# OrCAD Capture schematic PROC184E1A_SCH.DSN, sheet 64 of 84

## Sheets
64 71. OVER VOLTAGE PROTECTION CKT: size C; title: OVER VOLTAGE PROTECTION CKT; note: PROC184_SCH
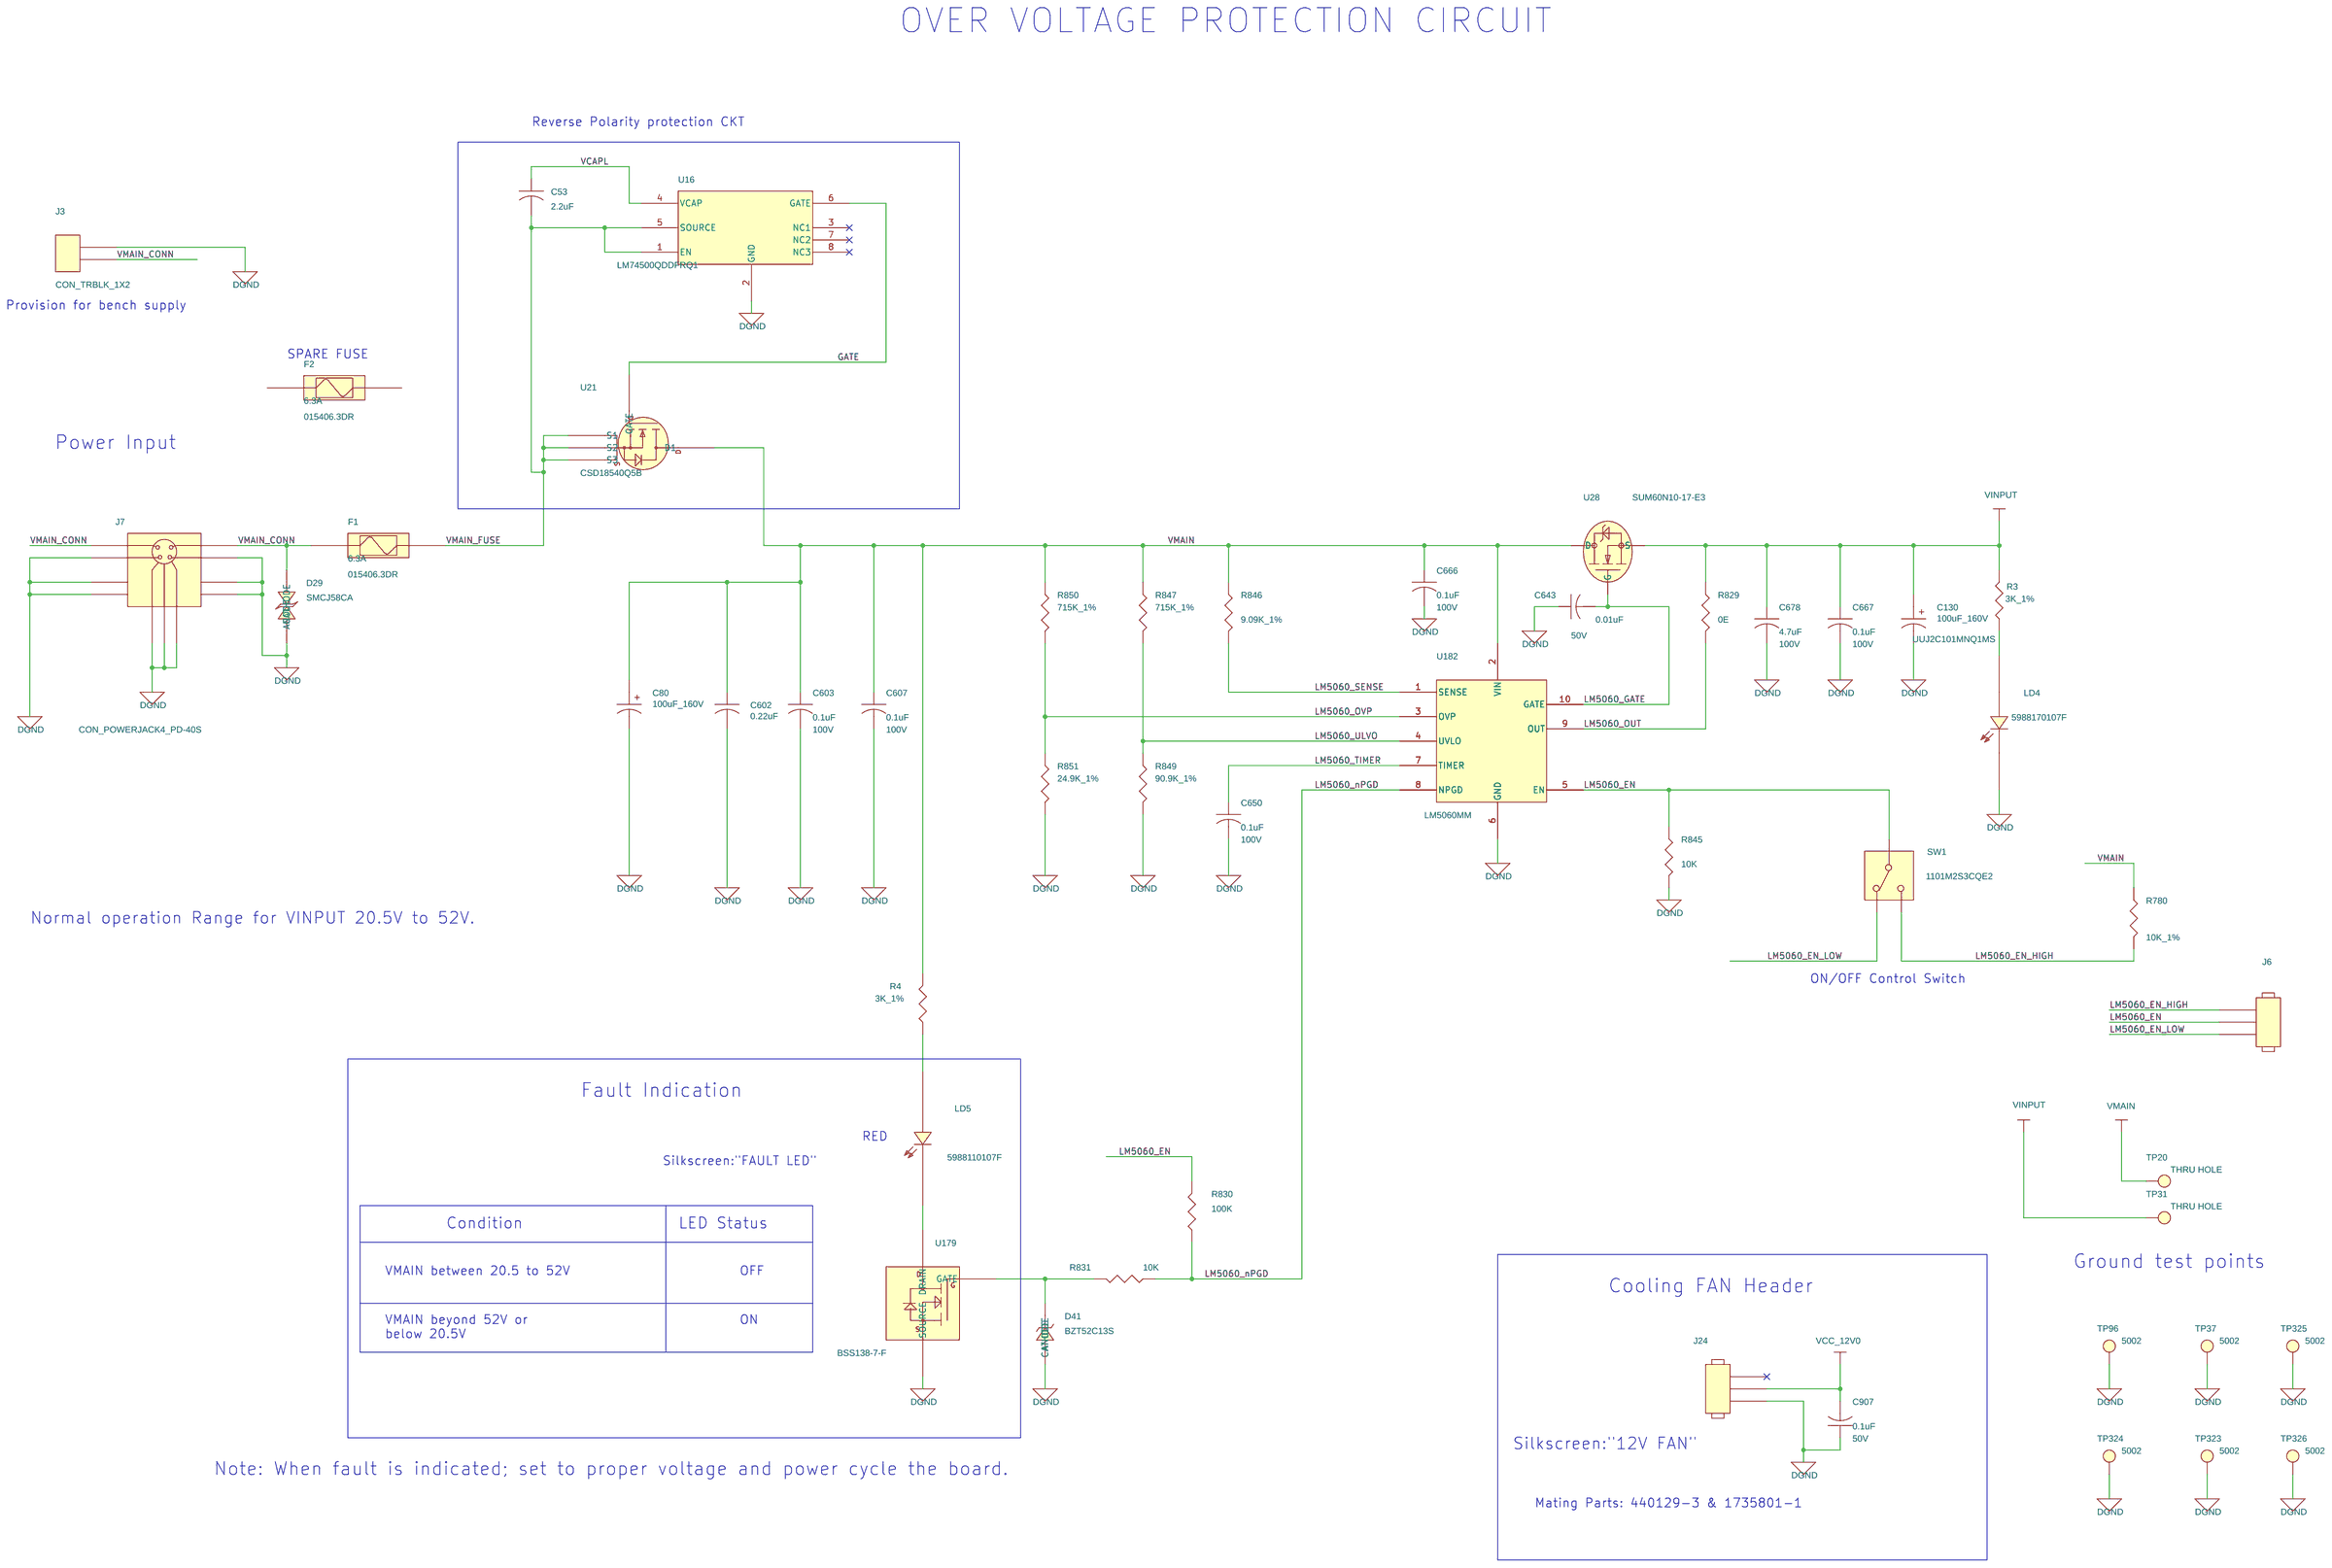
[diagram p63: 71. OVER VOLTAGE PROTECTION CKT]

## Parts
C53  2.2uF  [CAP1210_2-75]
C80  100uF_160V  [CAPAE_CASE173173_22-5]
C130  100uF_160V  [CAPAE_CASE173173_22-5]
C602  0.22uF  [CAP1206_1-25]
C603  0.1uF  [CAP0603_1]
C607  0.1uF  [CAP0603_1]
C643  0.01uF  [CAP0402_0-75]
C650  0.1uF  [CAP0603_1]
C666  0.1uF  [CAP0603_1]
C667  0.1uF  [CAP0603_1]
C678  4.7uF  [CAP1206_2]
C907  0.1uF  [CAP0402_0-75]
D29  SMCJ58CA  [DIO_SMC_2-7]
D41  BZT52C13S  [DIO_SOD323]
F1  6.3A  [FUSEH_154004_380X200_SMD_3-9]
F2  6.3A  [FUSEH_154004_380X200_SMD_3-9]
J3  CON_TRBLK_1X2  [CON_TB1X2_1803277_P_R_T_7-3]
J6  HDR_1X3  [HDR_3X1_100_S_T]
J7  CON_POWERJACK4_PD-40S  [CON_POWERJACK4_PD-40S_S_R_T_15]
J24  HDR_1X3  [HDR_1X3_440054-3_S_T_6-4]
LD4  5988170107F  [LED_0805_0-7]
LD5  5988110107F  [LED_0805]
R3  3K_1%  [RES0402_0-5]
R4  3K_1%  [RES0402_0-5]
R780  10K_1%  [RES0402_0-5]
R829  0E  [RES0402_0-5]
R830  100K  [RES0402_0-5]
R831  10K  [RES0402_0-5]
R845  10K  [RES0402_0-5]
R846  9.09K_1%  [RES0402_0-5]
R847  715K_1%  [RES0402_0-5]
R849  90.9K_1%  [RES0402_0-5]
R850  715K_1%  [RES0402_0-5]
R851  24.9K_1%  [RES0402_0-5]
SW1  1101M2S3CQE2  [SW3_185_500X260_TH_13]
TP20  THRU HOLE  [TP_40X65]
TP31  THRU HOLE  [TP_40X65]
TP37  5002  [TP_CIR67D40_TH_4-6]
TP96  5002  [TP_CIR67D40_TH_4-6]
TP323  5002  [TP_CIR67D40_TH_4-6]
TP324  5002  [TP_CIR67D40_TH_4-6]
TP325  5002  [TP_CIR67D40_TH_4-6]
TP326  5002  [TP_CIR67D40_TH_4-6]
U16  LM74500QDDFRQ1  [SOT23-8_1-1]
U21  CSD18540Q5B  [VSON8_CSD1850_240X200_1-1]
U28  SUM60N10-17-E3  [D2PAK-3]
U179  BSS138-7-F  [SOT23-123_1-1]
U182  LM5060MM  [MSOP10_19-68_120X120_1-1]

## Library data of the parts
C53 = CAP: CAP CERAMIC 2.2uF 100V 10% X7R 1210; Chkd/date: BAVISH/020811; Crtd /date: CHAITHANYA/290711; Custom_Duty: 15%; Customs_HS_Code: 85322990; Distributor_name: DIGIKEY; Distributor_part_number: 490-3385-1-ND; Footprint Path: Y:\MIS_DATABASE\Library\ALTIUM_TOOL\PCB_FOOTPRINTS\Altium_Footprint_Lib.PcbLib; Height: 2.70MM; Library Path: Y:\MIS_DATABASE\Library\ALTIUM_TOOL\SCHEMATICS_PARTS\MS_DISCRETE_Library.schlib; Manufacturer: MURATA; Mfr_name: MURATA; Mfr_part_number: GRM32ER72A225KA35L; Mistral Part No: 120011080001-R; Package: 1210; Part_type: CAPACITORS\CERAMIC; Project: ACRO_DM3730; RoHS: RoHS; Temperature: -55°C+125°C; Tolerance: 10%; Voltage: 100V; Wattage: NA; Weight: 110mg; Datasheet: Y:\MIS_DATABASE\DATASHEETS\CAPACITORS\MURATA-GXX-SER_NOV17.PDF
C80 C130 = CAP_POL: CAP ELECTROLYTIC 100uF 160V 20% CASE_173173; Chkd/date: MANIRAJA/110222; Crtd /date: ALVY/100222; Custom_Duty: 15%; Customs_HS_Code: 85322990; Distributor_name: MOUSER; Distributor_part_number: 647-UUJ2C101MNQ1MS; Footprint Path: Y:\MIS_DATABASE\Library\ALTIUM_TOOL\PCB_FOOTPRINTS\Altium_Footprint_Lib.PcbLib; Height: 22.50MM; Library Path: Y:\MIS_DATABASE\Library\ALTIUM_TOOL\SCHEMATICS_PARTS\MS_DISCRETE_Library.schlib; Manufacturer: NICHICON; Mfr_name: NICHICON; Mfr_part_number: UUJ2C101MNQ1MS; Mistral Part No: 120022020007-R; Package: CASE_173173; Part_type: CAPACITORS\ELECTROLYTIC; Project: TI_J7AHP_EVM_BRD; RoHS: RoHS; Temperature: -40°C+105°C; Tolerance: 20%; Voltage: 160V; Wattage: NA; Weight: 6170mg; Datasheet: Y:\MIS_DATABASE\DATASHEETS\CAPACITORS\UUJ-SER.PDF
C602 = CAP: CAP CERAMIC 0.22uF 100V 10% X7R 1206; Chkd/date: MAZHAR/151208; Crtd /date: USMAN/311008; Custom_Duty: 15%; Customs_HS_Code: 85322990; Distributor_name: DIGIKEY; Distributor_part_number: 490-3366-1-ND; Footprint Path: Y:\MIS_DATABASE\Library\ALTIUM_TOOL\PCB_FOOTPRINTS\Altium_Footprint_Lib.PcbLib; Height: 1.25MM; Library Path: Y:\MIS_DATABASE\Library\ALTIUM_TOOL\SCHEMATICS_PARTS\MS_DISCRETE_Library.schlib; Manufacturer: MURATA; Mfr_name: MURATA; Mfr_part_number: GRM31MR72A224KA01L; Mistral Part No: 120009030093-R; Package: 1206; Part_type: CAPACITORS\CERAMIC; Project: LADC_PB; RoHS: RoHS; Temperature: -55°C+125°C; Tolerance: 10%; Voltage: 100V; Wattage: NA; Weight: 40mg; Datasheet: Y:\MIS_DATABASE\DATASHEETS\CAPACITORS\MURATA-GXX-SER_NOV17.PDF
C603 C607 = CAP: CAP CERAMIC 0.1uF 100V 10% X7R 0603; Automotive Alternate_mfr_name: TDK; Automotive Alternate_mfr_part_number: CGA3E2X7R1H104K080AA; Chkd/date: MANIRAJA/170420; Crtd /date: ALVY/170420; Custom_Duty: 15%; Customs_HS_Code: 85322990; Direct Alternate_mfr_name: SAMSUNG; Direct Alternate_mfr_part_number: CL10B104JB8NNNC; Distributor_name: DIGIKEY; Distributor_part_number: 490-3285-1-ND; Footprint Path: Y:\MIS_DATABASE\Library\ALTIUM_TOOL\PCB_FOOTPRINTS\Altium_Footprint_Lib.PcbLib; Height: 0.90MM; Library Path: Y:\MIS_DATABASE\Library\ALTIUM_TOOL\SCHEMATICS_PARTS\MS_DISCRETE_Library.schlib; Manufacturer: MURATA; Mfr_name: MURATA; Mfr_part_number: GRM188R72A104KA35D; Mistral Part No: 120017010012-R; Package: 0603; Part_type: CAPACITORS\CERAMIC; Project: CUSTOM DCA1000; RoHS: RoHS; Temperature: -55°C+125°C; Tolerance: 10%; Voltage: 100V; Wattage: NA; Weight: 6.3mg; Datasheet: Y:\MIS_DATABASE\DATASHEETS\CAPACITORS\GRM188R72A104KA35.PDF
C643 = CAP: CAP CERAMIC 0.01uF 50V 10% X7R 0402; Assembly_Instruction: DNI; Automotive Alternate_mfr_name: TDK; Automotive Alternate_mfr_part_number: CGA2B3X7R1H103K050BB; Chkd/date: MANIRAJA/280319; Crtd /date: MANIRAJA/280319; Custom_Duty: 15%; Customs_HS_Code: 85322990; Direct Alternate_mfr_name: TDK; Direct Alternate_mfr_part_number: C1005X7R1H103K050BE; Distributor_name: DIGIKEY; Distributor_part_number: 490-4516-1-ND; Footprint Path: Y:\MIS_DATABASE\Library\ALTIUM_TOOL\PCB_FOOTPRINTS\Altium_Footprint_Lib.PcbLib; Height: 0.55MM; Library Path: Y:\MIS_DATABASE\Library\ALTIUM_TOOL\SCHEMATICS_PARTS\MS_DISCRETE_Library.schlib; Manufacturer: MURATA; Mfr_name: MURATA; Mfr_part_number: GRM155R71H103KA88D; Mistral Part No: 120009030025-R; Package: 0402; Part_type: CAPACITORS\CERAMIC; Project: G4_SVGA; RoHS: RoHS; Temperature: -55°C+125°C; Tolerance: 10%; Voltage: 50V; Wattage: NA; Weight: 0.65mg; Datasheet: Y:\MIS_DATABASE\DATASHEETS\CAPACITORS\GRM155R71H103KA88D.PDF
C650 C666 C667 = CAP: CAP CERAMIC 0.1uF 100V 10% X7R 0603; Automotive Alternate_mfr_name: TDK; Automotive Alternate_mfr_part_number: CGA3E2X7R1H104K080AA; Chkd/date: MANIRAJA/170420; Crtd /date: ALVY/170420; Custom_Duty: 15%; Customs_HS_Code: 85322990; DescriptiveText: CAP CERAMIC 0.1uF 100V 10% X7R 0603; Direct Alternate_mfr_name: SAMSUNG; Direct Alternate_mfr_part_number: CL10B104JB8NNNC; Distributor_name: DIGIKEY; Distributor_part_number: 490-3285-1-ND; Footprint Path: Y:\MIS_DATABASE\Library\ALTIUM_TOOL\PCB_FOOTPRINTS\Altium_Footprint_Lib.PcbLib; Height: 0.90MM; Library Path: Y:\MIS_DATABASE\Library\ALTIUM_TOOL\SCHEMATICS_PARTS\MS_DISCRETE_Library.schlib; Manufacturer: MURATA; Mfr: YAGEO AMERICA; MfrNum: CC0603KRX7R0BB104; Mfr_name: MURATA; Mfr_part_number: GRM188R72A104KA35D; Mistral Part No: 120017010012-R; Mistral part number: NSPN00374; Package: 0603; Part_type: CAPACITORS\CERAMIC; Project: CUSTOM DCA1000; RoHS: RoHS; Temperature: -55°C+125°C; Tolerance: 10%; Voltage: 100V; Wattage: NA; Weight: 6.3mg; Datasheet: Y:\MIS_DATABASE\DATASHEETS\CAPACITORS\GRM188R72A104KA35.PDF
C678 = CAP: CAP CERAMIC 4.7uF 100V 10% X7S 1206; Automotive Alternate_mfr_name: TDK; Automotive Alternate_mfr_part_number: CGA4J1X7R1H475K125AC; Chkd/date: MANIRAJA/121020; Crtd /date: ALVY/091020; Custom_Duty: 15%; Customs_HS_Code: 85322990; Direct Alternate_mfr_name: MURATA; Direct Alternate_mfr_part_number: GRM21BR61H475KE51L; Distributor_name: DIGIKEY; Distributor_part_number: 490-18620-1-ND; Footprint Path: Y:\MIS_DATABASE\Library\ALTIUM_TOOL\PCB_FOOTPRINTS\Altium_Footprint_Lib.PcbLib; Height: 1.90MM; Library Path: Y:\MIS_DATABASE\Library\ALTIUM_TOOL\SCHEMATICS_PARTS\MS_DISCRETE_Library.schlib; Manufacturer: MURATA; Mfr_name: MURATA; Mfr_part_number: GRM31CC72A475KE11L; Mistral Part No: 120020100021-R; Package: 1206; Part_type: CAPACITORS\CERAMIC; Project: ECU_RO; RoHS: RoHS; Temperature: -55°C+125°C; Tolerance: 10%; Voltage: 100V; Wattage: NA; Weight: 64mg; Datasheet: Y:\MIS_DATABASE\DATASHEETS\CAPACITORS\GRM31CC72A475KE11.PDF
C907 = CAP: CAP CERAMIC 0.1uF 50V 10% X7R 0402; Automotive Alternate_mfr_name: TDK; Automotive Alternate_mfr_part_number: CGA2B3X7R1H104K050BB; Chkd/date: MANIRAJA/261020; Crtd /date: ALVY/211020; Custom_Duty: 15%; Customs_HS_Code: 85322990; Direct Alternate_mfr_name: TDK; Direct Alternate_mfr_part_number: C1005X7R1H104K050BE; Distributor_name: DIGIKEY; Distributor_part_number: 490-10700-1-ND; Footprint Path: Y:\MIS_DATABASE\Library\ALTIUM_TOOL\PCB_FOOTPRINTS\Altium_Footprint_Lib.PcbLib; Height: 0.55MM; Library Path: Y:\MIS_DATABASE\Library\ALTIUM_TOOL\SCHEMATICS_PARTS\MS_DISCRETE_Library.schlib; Manufacturer: MURATA; Mfr_name: MURATA; Mfr_part_number: GRM155R71H104KE14D; Mistral Part No: 120011100014-R; Package: 0402; Part_type: CAPACITORS\CERAMIC; Project: J7_CP; RoHS: RoHS; Temperature: -55°C+125°C; Tolerance: 10%; Voltage: 50V; Wattage: NA; Weight: 3.1mg; Datasheet: Y:\MIS_DATABASE\DATASHEETS\CAPACITORS\GRM155R71H104KE14.PDF
D29 = DIODE_TVS_DUAL: DIODE TVS BI-DIR 1500W 58V SMC; Chkd/date: ALVY/210222; Crtd /date: TAMILARASU/210222; Custom_Duty: 15%; Customs_HS_Code: 85412900; Distributor_name: DIGIKEY; Distributor_part_number: SMCJ58CALFCT-ND; Footprint Path: Y:\MIS_DATABASE\Library\ALTIUM_TOOL\PCB_FOOTPRINTS\Altium_Footprint_Lib.PcbLib; Height: 2.62MM; Library Path: Y:\MIS_DATABASE\Library\ALTIUM_TOOL\SCHEMATICS_PARTS\MS_DISCRETE_Library.schlib; Manufacturer: LITTELFUSE; Mfr_name: LITTELFUSE; Mistral Part No: 130022020036-R; Package: SMC; Part_type: DIODE\TVS; Project: TI_J7AHP_EVM_BRD; RoHS: RoHS; Temperature: -65°C+150°C; Tolerance: NA; Voltage: 58V; Wattage: NA; Weight: 210mg; Datasheet: Y:\MIS_DATABASE\DATASHEETS\DISCRETES\DIODES\LF-SMCJ-SER.PDF
D41 = DIODE_ZENER: DIODE ZENER 13V 200mW SOD323; Chkd/date: MAZHAR/101210; Crtd /date: BAVISH/101210; Custom_Duty: 15%; Customs_HS_Code: 85412900; Distributor_name: DIGIKEY; Distributor_part_number: BZT52C13S-FDICT-ND; Height: 1.05MM; Manufacturer: DIODES INC; Mfr_name: DIODES INC; Mfr_part_number: BZT52C13S-7-F; Mistral Part No: 130010120013-R; Package: SOD323; Part_type: DIODE\ZENER; Project: IEMS; RoHS: RoHS; Temperature: -65°C+150°C; Tolerance: NA; Voltage: NA; Wattage: 200mW; Weight: 0.004g; Datasheet: Y:\MIS_DATABASE\DATASHEETS\DISCRETES\DIODES\BZT52C.PDF
F1 F2 = FUSE_HOLDER_0154: FUSE AND HOLDER BLOK 6.3A SMD; Chkd/date: USMAN/280612; Crtd /date: BAVISH/040811; Custom_Duty: NA; Customs_HS_Code: NA; Distributor_name: DIGIKEY; Distributor_part_number: F3152CT-ND; Footprint Path: Y:\MIS_DATABASE\Library\ALTIUM_TOOL\PCB_FOOTPRINTS\Altium_Footprint_Lib.PcbLib; Height: 3.81MM; Library Path: Y:\MIS_DATABASE\Library\ALTIUM_TOOL\SCHEMATICS_PARTS\MS_DISCRETE_Library.schlib; Mfr_name: LITTLE FUSE; Mfr_part_number: 015406.3DR; Mistral Part No: 130011080014-R; Package: SMD; Part_type: FUSE; Project: GEMYC; RoHS: RoHS; Temperature: -55°C+125°C; Tolerance: NA; Voltage: NA; Wattage: NA; Weight: NA; Datasheet: Y:\MIS_DATABASE\DATASHEETS\MISC\FUSE\0154X-SER.PDF
J3 = CON_TRBLK_2X1: CON TERMINAL BLOCKS 1X2 3.81MM PITCH MALE RT TH; Chkd/date: ALVY/140322; Crtd /date: TAMILARASU/110322; Custom_Duty: 24%; Customs_HS_Code: 85369090; Distributor_name: DIGIKEY; Distributor_part_number: 277-1206-ND; Footprint Path: Y:\MIS_DATABASE\Library\ALTIUM_TOOL\PCB_FOOTPRINTS\Altium_Footprint_Lib.PcbLib; Height: 7.25MM; Library Path: Y:\MIS_DATABASE\Library\ALTIUM_TOOL\SCHEMATICS_PARTS\MS_CONNECTOR_Library.schlib; Mfr_name: PHOENIX; Mfr_part_number: 1803277; Mistral Part No: 150022030013-R; Package: THRU-HOLE; Part_type: CONNECTOR\TERMINAL BLOCK; Project: TI_J7AHP_EVM_BRD; RoHS: RoHS; Temperature: NA; Tolerance: NA; Voltage: NA; Wattage: NA; Weight: 784mg; Datasheet: Y:\MIS_DATABASE\DATASHEETS\CONNECTORS\1803277.PDF
J6 = HEADER_3X1: HDR 1X3 2.54MM PITCH ST TH; Assembly_Instruction: DNI; Chkd/date: VASANTHA/290616; Crtd /date: VASANTHA/290616; Custom_Duty: 15%; Customs_HS_Code: 85322990; Distributor_name: DIGIKEY; Distributor_part_number: 609-3471-ND; Height: 8.58MM; Manufacturer: FCI; Mfr_name: FCI; Mfr_part_number: 68001-403HLF; Mistral Part No: 150016060025-R; Package: THRU-HOLE; Part_type: CONNECTOR\HEADERS; Project: IKEYP; RoHS: RoHS; Temperature: -40°C+105°C; Tolerance: NA; Voltage: NA; Wattage: NA; Weight: NA; Datasheet: Y:\MIS_DATABASE\DATASHEETS\CONNECTORS\68000.PDF
J7 = CON_POWERJACK_PD-40S: CON POWER JACK 4POS FEMALE RT TH; Chkd/date: VASANTHA/140616; Crtd /date: VASANTHA/140616; Custom_Duty: 24%; Customs_HS_Code: 85369090; Distributor_name: DIGIKEY; Distributor_part_number: CP-7240-ND; Height: 15.00MM; Manufacturer: CUI INC; Mfr_name: CUI INC; Mfr_part_number: PD-40S; Mistral Part No: 150016060015-R; Package: THRU-HOLE; Part_type: CONNECTOR\JACK; Project: NTR_GPSDO BOX CARD; RoHS: RoHS; Temperature: NA; Tolerance: NA; Voltage: NA; Wattage: NA; Weight: NA; Datasheet: Y:\MIS_DATABASE\DATASHEETS\CONNECTORS\PD-40S.PDF
J24 = HEADER_3X1: CON HDR 1X3 2.00MM PITCH ST TH; Chkd/date: MANIRAJA/261017; Crtd /date: MANIRAJA/261017; Custom_Duty: 24%; Customs_HS_Code: 85369090; Distributor_name: DIGIKEY; Distributor_part_number: A100035-ND; Height: 6.35MM; Manufacturer: TE CONNECTIVITY; Mfr_name: TE CONNECTIVITY; Mfr_part_number: 440054-3; Mistral Part No: 150017100038-R; Package: THRU-HOLE; Part_type: CONNECTOR\HEADERS; Project: TI_MAXIE_CPB; RoHS: RoHS; Temperature: -25°C+85°C; Tolerance: NA; Voltage: NA; Wattage: NA; Weight: NA; Datasheet: Y:\MIS_DATABASE\DATASHEETS\CONNECTORS\440054XXX.PDF
LD4 = LED_598-8170-107F: LED ALINGAP GREEN CLEAR 0805; Chkd/date: MANIRAJA/230817; Crtd /date: SARANYA/070514; Custom_Duty: 24%; Customs_HS_Code: 85437099; Distributor_name: DIGIKEY; Distributor_part_number: 350-2044-1-ND; Footprint Path: Y:\MIS_DATABASE\Library\ALTIUM_TOOL\PCB_FOOTPRINTS\Altium_Footprint_Lib.PcbLib; Height: 0.70MM; Manufacturer: DIALIGHT; Mfr_name: DIALIGHT; Mistral Part No: 130014050065-R; Package: 0805; Part_type: OPTO\LED; Project: AEGIS GP BETA2; RoHS: RoHS; Temperature: -30°C+85°C; Tolerance: NA; Voltage: NA; Wattage: NA; Weight: NA; Datasheet: Y:\MIS_DATABASE\DATASHEETS\DISCRETES\LEDS\598-SER.PDF
LD5 = LED_598-8170-107F: LED ALINGAP RED CLEAR 0805 SMD; Chkd/date: BALACHANDAR/160514; Crtd /date: SARANYA/070514; Custom_Duty: 24%; Customs_HS_Code: 85437099; Distributor_name: DIGIKEY; Distributor_part_number: 350-2038-1-ND; Footprint Path: Y:\MIS_DATABASE\Library\ALTIUM_TOOL\PCB_FOOTPRINTS\Altium_Footprint_Lib.PcbLib; Height: 0.70MM; Manufacturer: DIALIGHT; Mfr_name: DIALIGHT; Mistral Part No: 130014050069-R; Package: 0805; Part_type: OPTO\LED; Project: AEGIS GP BETA2; RoHS: RoHS; Temperature: NA; Tolerance: NA; Voltage: NA; Wattage: NA; Weight: NA; Datasheet: Y:\MIS_DATABASE\DATASHEETS\DISCRETES\LEDS\598-SER.PDF
R3 R4 = RESISTOR: RES 3K 1/16W 1% 0402; Chkd/date: MANIRAJA/101117; Crtd /date: MANIRAJA/101117; Custom_Duty: 15%; Customs_HS_Code: 85332119; Distributor_name: DIGIKEY; Distributor_part_number: 311-3KLRCT-ND; Footprint Path: Y:\MIS_DATABASE\Library\ALTIUM_TOOL\PCB_FOOTPRINTS\Altium_Footprint_Lib.PcbLib; Height: 0.40MM; Library Path: Y:\MIS_DATABASE\Library\ALTIUM_TOOL\SCHEMATICS_PARTS\MS_DISCRETE_Library.schlib; Manufacturer: YAGEO AMERICA; Mfr_name: YAGEO AMERICA; Mfr_part_number: RC0402FR-073KL; Mistral Part No: 110017110004-R; Package: 0402; Part_type: RESISTORS\FIXED; Project: TI_SVB_MAXWELL_DUT; RoHS: RoHS; Temperature: -55°C+155°C; Tolerance: 1%; Voltage: NA; Wattage: 1/16W; Weight: 0.65mg; Datasheet: Y:\MIS_DATABASE\DATASHEETS\RESISTORS\RCXXXXL-SER_MAR18.PDF
R780 = RESISTOR: RES 10K 1/16W 1% 0402; Chkd/date: VASANTHA/201216; Crtd /date: GEETHA/290506; Custom_Duty: 15%; Customs_HS_Code: 85332119; Distributor_name: DIGIKEY; Distributor_part_number: 311-10.0KLRTR-ND; Footprint Path: Y:\MIS_DATABASE\Library\ALTIUM_TOOL\PCB_FOOTPRINTS\Altium_Footprint_Lib.PcbLib; Height: 0.40MM; Library Path: Y:\MIS_DATABASE\Library\ALTIUM_TOOL\SCHEMATICS_PARTS\MS_DISCRETE_Library.schlib; Manufacturer: YAGEO AMERICA; Mfr_name: YAGEO AMERICA; Mfr_part_number: RC0402FR-0710KL; Mistral Part No: 110015090015-R; Package: 0402; Part_type: RESISTORS\FIXED; Project: VOCERA; RoHS: RoHS; Temperature: -55°C+155°C; Tolerance: 1%; Voltage: NA; Wattage: 1/16W; Weight: 0.65mg; Datasheet: Y:\MIS_DATABASE\DATASHEETS\RESISTORS\RCXXXXL-SER_MAR18.PDF
R829 = RESISTOR: RES 0E 1/10W JUMPER 0402; Chkd/date: VASANTHA/061216; Crtd /date: NAVEED/201014; Custom_Duty: 15%; Customs_HS_Code: 85332119; Distributor_name: DIGIKEY; Distributor_part_number: P0.0JCT-ND; Footprint Path: Y:\MIS_DATABASE\Library\ALTIUM_TOOL\PCB_FOOTPRINTS\Altium_Footprint_Lib.PcbLib; Height: 0.40MM; IBISSP_MODLES: VALUE REPEATING 2 TIME; Library Path: Y:\MIS_DATABASE\Library\ALTIUM_TOOL\SCHEMATICS_PARTS\MS_DISCRETE_Library.schlib; Manufacturer: PANASONIC-ECG; Mfr_name: PANASONIC-ECG; Mfr_part_number: ERJ-2GE0R00X; Mistral Part No: 110018030052-R; Package: 0402; Part_type: RESISTORS\FIXED; Project: AEGIS POM; RoHS: RoHS; Temperature: -55°C+155°C; Tolerance: NA; Voltage: NA; Wattage: 1/10W; Weight: 0.8mg; Datasheet: Y:\MIS_DATABASE\DATASHEETS\RESISTORS\PAN-ERJSER_NOV17.PDF
R830 = RESISTOR: RES 100K 1/10W 5% 0402; Chkd/date: VASANTHA/291216; Crtd /date: GEETHA/190406; Custom_Duty: 15%; Customs_HS_Code: 85332119; Distributor_name: DIGIKEY; Distributor_part_number: P100KJCT-ND; Footprint Path: Y:\MIS_DATABASE\Library\ALTIUM_TOOL\PCB_FOOTPRINTS\Altium_Footprint_Lib.PcbLib; Height: 0.40MM; Library Path: Y:\MIS_DATABASE\Library\ALTIUM_TOOL\SCHEMATICS_PARTS\MS_DISCRETE_Library.schlib; Manufacturer: PANASONIC-ECG; Mfr_name: PANASONIC-ECG; Mfr_part_number: ERJ-2GEJ104X; Mistral Part No: 110009030177-R; Package: 0402; Part_type: RESISTORS\FIXED; Project: RED EYE; RoHS: RoHS; Temperature: -55°C+155°C; Tolerance: 5%; Voltage: NA; Wattage: 1/10W; Weight: 0.8mg; Datasheet: Y:\MIS_DATABASE\DATASHEETS\RESISTORS\PAN-ERJSER_NOV17.PDF
R831 R845 = RESISTOR: RES 10K 1/16W 5% 0402; Chkd/date: VASANTHA/061216; Crtd /date: MAZHAR/230805; Custom_Duty: 15%; Customs_HS_Code: 85332119; Distributor_name: DIGIKEY; Distributor_part_number: 311-10KJRCT-ND; Footprint Path: Y:\MIS_DATABASE\Library\ALTIUM_TOOL\PCB_FOOTPRINTS\Altium_Footprint_Lib.PcbLib; Height: 0.40MM; Library Path: Y:\MIS_DATABASE\Library\ALTIUM_TOOL\SCHEMATICS_PARTS\MS_DISCRETE_Library.schlib; Manufacturer: YAGEO AMERICA; Mfr_name: YAGEO AMERICA; Mfr_part_number: RC0402JR-0710KL; Mistral Part No: 110011060021-R; Package: 0402; Part_type: RESISTORS\FIXED; Project: HSE; RoHS: RoHS; Temperature: -55°C+155°C; Tolerance: 5%; Voltage: NA; Wattage: 1/16W; Weight: 0.65mg; Datasheet: Y:\MIS_DATABASE\DATASHEETS\RESISTORS\RCXXXXL-SER_MAR18.PDF
R846 = RESISTOR: RES 9.09K 1/16W 1% 0402; Chkd/date: VASANTHA/281216; Crtd /date: BAVISH/010611; Custom_Duty: 15%; Customs_HS_Code: 85332119; Distributor_name: DIGIKEY; Distributor_part_number: 541-9.09KLCT-ND; Footprint Path: Y:\MIS_DATABASE\Library\ALTIUM_TOOL\PCB_FOOTPRINTS\Altium_Footprint_Lib.PcbLib; Height: 0.40MM; Library Path: Y:\MIS_DATABASE\Library\ALTIUM_TOOL\SCHEMATICS_PARTS\MS_DISCRETE_Library.schlib; Manufacturer: VISHAY; Mfr_name: VISHAY; Mfr_part_number: CRCW04029K09FKED; Mistral Part No: 110011060006-R; Package: 0402; Part_type: RESISTORS\FIXED; Project: TE_MODULE; RoHS: RoHS; Temperature: -55°C+155°C; Tolerance: 1%; Voltage: NA; Wattage: 1/16W; Weight: 0.65mg; Datasheet: Y:\MIS_DATABASE\DATASHEETS\RESISTORS\CRCW0603.PDF
R847 R850 = RESISTOR: RES 715K 1/10W 1% 0402; Chkd/date: JEBRAN/040715; Crtd /date: JEBRAN/040715; Custom_Duty: 15%; Customs_HS_Code: 85332119; Distributor_name: DIGIKEY; Distributor_part_number: P715KLCT-ND; Footprint Path: Y:\MIS_DATABASE\Library\ALTIUM_TOOL\PCB_FOOTPRINTS\Altium_Footprint_Lib.PcbLib; Height: 0.40MM; Library Path: Y:\MIS_DATABASE\Library\ALTIUM_TOOL\SCHEMATICS_PARTS\MS_DISCRETE_Library.schlib; Mfr_name: PANASONIC-ECG; Mfr_part_number: ERJ-2RKF7153X; Mistral Part No: 110015070005-R; Package: 0402; Part_type: RESISTORS\FIXED; Project: CYPHY_FVB; RoHS: RoHS; Temperature: -55°C+155°C; Tolerance: 1%; Voltage: NA; Wattage: 1/10W; Weight: 0.8mg; Datasheet: Y:\MIS_DATABASE\DATASHEETS\RESISTORS\PAN-ERJSER_NOV17.PDF
R849 = RESISTOR: RES 90.9K 1/10W 1% 0402; Chkd/date: ALVY/210222; Crtd /date: TAMILARASU/210222; Custom_Duty: 15%; Customs_HS_Code: 85332119; Distributor_name: DIGIKEY; Distributor_part_number: 2019-RK73G1ETTP9092FCT-ND; Footprint Path: Y:\MIS_DATABASE\Library\ALTIUM_TOOL\PCB_FOOTPRINTS\Altium_Footprint_Lib.PcbLib; Height: 0.40MM; Library Path: Y:\MIS_DATABASE\Library\ALTIUM_TOOL\SCHEMATICS_PARTS\MS_DISCRETE_Library.schlib; Manufacturer: YAGEO AMERICA; Mfr_name: KOA SPEER; Mfr_part_number: RK73G1ETTP9092F; Mistral Part No: 110022020011-R; Package: 0402; Part_type: RESISTORS\FIXED; Project: TI_J7AHP_EVM_BRD; RoHS: RoHS; Temperature: -55°C+155°C; Tolerance: 1%; Voltage: NA; Wattage: 1/10W; Weight: 0.65mg; Datasheet: Y:\MIS_DATABASE\DATASHEETS\RESISTORS\RK73G-SER.PDF
R851 = RESISTOR: RES 24.9K 1/16W 1% 0402; Chkd/date: MANIRAJA/121017; Crtd /date: MANIRAJA/121017; Custom_Duty: 15%; Customs_HS_Code: 85332119; Distributor_name: DIGIKEY; Distributor_part_number: 311-24.9KLRCT-ND; Footprint Path: Y:\MIS_DATABASE\Library\ALTIUM_TOOL\PCB_FOOTPRINTS\Altium_Footprint_Lib.PcbLib; Height: 0.40MM; Library Path: Y:\MIS_DATABASE\Library\ALTIUM_TOOL\SCHEMATICS_PARTS\MS_DISCRETE_Library.schlib; Manufacturer: YAGEO AMERICA; Mfr_name: YAGEO AMERICA; Mfr_part_number: RC0402FR-0724K9L; Mistral Part No: 110009030538-R; Package: 0402; Part_type: RESISTORS\FIXED; Project: P4_RADAR_DI; RoHS: RoHS; Temperature: -55°C+155°C; Tolerance: 1%; Voltage: NA; Wattage: 1/16W; Weight: 0.65mg; Datasheet: Y:\MIS_DATABASE\DATASHEETS\RESISTORS\RCXXXXL-SER_MAR18.PDF
SW1 = SW3_SPDT_1101: SWITCH MINIATURE SLIDE SPDT VERTICAL TH; Chkd/date: VASANTHA/060117; Crtd /date: BAVISH/130711; Custom_Duty: 24%; Customs_HS_Code: 85369090; Distributor_name: DIGIKEY; Distributor_part_number: CKN5001-ND; Height: 12.98MM; Manufacturer: C&K COMPONENTS; Mfr_name: C&K COMPONENTS; Mistral Part No: 130011070018-R; Package: THRU-HOLE; Part_type: ELECTRO-MECHANICAL\SWITCH; Project: HMC_DEBUG; RoHS: RoHS; Temperature: -30°C+65°C; Tolerance: NA; Voltage: NA; Wattage: NA; Weight: NA; Datasheet: Y:\MIS_DATABASE\DATASHEETS\MISC\SWITCHES\1101-SERIES.PDF
TP20 TP31 = TESTPOINT: TESTPOINT 1.0MM DRILL PTH; Chkd/date: MAZHAR/271211; Crtd /date: SHREESHAIL/041005; Distributor_name: NA; Distributor_part_number: NA; Height: NA; Manufacturer: LOCAL; Mfr_name: LOCAL; Mistral Part No: 130009030938; Package: THRU-HOLE; Project: HSE; Datasheet: NA
TP37 TP96 TP323-TP326 = TESTPOINT: ACCESSORIE PC TEST POINT; Chkd/date: VASANTHA/121216; Crtd /date: MANIRAJA/121216; Custom_Duty: NA; Customs_HS_Code: NA; Distributor_name: DIGIKEY; Distributor_part_number: 36-5002-ND; Footprint Path: Y:\MIS_DATABASE\Library\ALTIUM_TOOL\PCB_FOOTPRINTS\Altium_Footprint_Lib.PcbLib; Height: 4.57MM; Library Path: Y:\MIS_DATABASE\Library\ALTIUM_TOOL\SCHEMATICS_PARTS\MS_DISCRETE_Library.schlib; Manufacturer: KEYSTONE; Mfr_name: KEYSTONE; Mistral Part No: 160016120008-R; Package: NA; Part_type: ACCESSORIES; Project: EPOS_EVM; RoHS: RoHS; Temperature: NA; Tolerance: NA; Voltage: NA; Wattage: NA; Weight: NA; Datasheet: Y:\MIS_DATABASE\DATASHEETS\MISC\ACCESSORIES\5002.PDF
U16 = LM74500QDDFRQ1_SOT23-8: IC REVERSE POLARITY PROTECTION CONTROLLER SOT23-8; Chkd/date: MANIRAJA/160222; Crtd /date: TAMILARASU/160222; Custom_Duty: 15%; Customs_HS_Code: 85423100; Distributor_name: DIGIKEY; Distributor_part_number: 296-LM74500QDDFRQ1CT-ND; Footprint Path: Y:\MIS_DATABASE\Library\ALTIUM_TOOL\PCB_FOOTPRINTS\Altium_Footprint_Lib.PcbLib; Height: 1.10MM; Library Path: Y:\MIS_DATABASE\Library\ALTIUM_TOOL\SCHEMATICS_PARTS\MS_MISCPOWER_Library.schlib; Manufacturer: TEXAS INSTRUMENTS; Mfr_name: TEXAS INSTRUMENTS; Mistral Part No: 142022020017-R; Package: SOT23-8; Part_type: ICS\POWER\CONTROL; Project: TI_J7AHP_EVM_BRD; RoHS: RoHS; Temperature: -40°C+125°C; Tolerance: NA; Voltage: NA; Wattage: NA; Weight: NA; Datasheet: Y:\MIS_DATABASE\DATASHEETS\ICS\POWER\LM74500QDDFRQ1.PDF
U21 = MOSFET_CSD18501Q5A: IC 60V MOSFET N-CHANNEL NEXFET VSON8; Chkd/date: MANIRAJA/031219; Crtd /date: ALVY/031219; Custom_Duty: 15%; Customs_HS_Code: 85423100; Distributor_name: DIGIKEY; Distributor_part_number: 296-41076-1-ND; Footprint Path: Y:\MIS_DATABASE\Library\ALTIUM_TOOL\PCB_FOOTPRINTS\Altium_Footprint_Lib.PcbLib; Height: 1.05MM; Library Path: Y:\MIS_DATABASE\Library\ALTIUM_TOOL\SCHEMATICS_PARTS\MS_MOSFET_Library.schlib; Manufacturer: TEXAS INSTRUMENTS; Mfr_name: TEXAS INSTRUMENTS; Mistral Part No: 142019120002-R; Package: VSON8; Part_type: ICS\POWER\MOSFET; Project: CLOUD RADAR_CONTROLLER-PS_BRD; RoHS: RoHS; Temperature: -55°C+175°C; Tolerance: NA; Voltage: NA; Wattage: NA; Weight: NA; Datasheet: Y:\MIS_DATABASE\DATASHEETS\ICS\POWER\CSD18540Q5B.PDF
U28 = MOSFET_IRFZ24NS: IC POWER MOSFET N-CHANNEL D2PAK; Chkd/date: VASANTHA/101015; Crtd /date: VASANTHA/101015; Custom_Duty: 15%; Customs_HS_Code: 85423100; Distributor_name: DIGIKEY; Distributor_part_number: SUM60N10-17-E3CT-ND; Height: 4.82MM; Manufacturer: VISHAY; Mfr_name: VISHAY; Mistral Part No: 142015100008-R; Package: D2PAK; Part_type: ICS\POWER\MOSFET; Project: GALILEO_EVM; RoHS: RoHS; Temperature: -55°C+175°C; Tolerance: NA; Voltage: 100V; Wattage: NA; Weight: NA; Datasheet: Y:\MIS_DATABASE\DATASHEETS\DISCRETES\TRANSISTORS_FETS\SUM60N10.PDF
U179 = MOSFET_2N7002_SOT23_v2: IC MOSFET N-CHANNEL 50V 200mA SOT23-123; Chkd/date: MANIRAJA/190618; Crtd /date: USMAN/240709; Custom_Duty: 15%; Customs_HS_Code: 85423100; Distributor_name: DIGIKEY; Distributor_part_number: BSS138-FDICT-ND; Footprint Path: Y:\MIS_DATABASE\Library\ALTIUM_TOOL\PCB_FOOTPRINTS\Altium_Footprint_Lib.PcbLib; Height: 1.10MM; Library Path: Y:\MIS_DATABASE\Library\ALTIUM_TOOL\SCHEMATICS_PARTS\MS_MOSFET_Library.schlib; Library Ref: MOSFET_2N7002_SOT23; Manufacturer: DIODES INC; Mfr_name: DIODES INC; Mistral Part No: 142009070019-R; Package: SOT23-123; Part_type: ICS\POWER\MOSFET; Project: KHAN_MAIN; RoHS: RoHS; Temperature: -55°C+150°C; Tolerance: NA; Voltage: 50V; Wattage: 300mW; Weight: 8mg; Datasheet: Y:\MIS_DATABASE\DATASHEETS\DISCRETES\TRANSISTORS_FETS\BSS138.PDF
U182 = LM5060_MSOP10_TI: IC CONTROLLER HIGH-SIDE PROTECTION VSSOP10; Automotive Alternate_mfr_name: TEXAS INSTRUMENTS; Automotive Alternate_mfr_part_number: LM5060Q1MM/NOPB; Chkd/date: VASANTHA/101015; Crtd /date: VASANTHA/101015; Custom_Duty: 15%; Customs_HS_Code: 85423100; Distributor_name: DIGIKEY; Distributor_part_number: 296-39024-1-ND; Footprint Path: Y:\MIS_DATABASE\Library\ALTIUM_TOOL\PCB_FOOTPRINTS\Altium_Footprint_Lib.PcbLib; Height: 1.10MM; Library Path: Y:\MIS_DATABASE\Library\ALTIUM_TOOL\SCHEMATICS_PARTS\MS_MISCPOWER_Library.schlib; Library Ref: LM5060_MSOP10; Manufacturer: TEXAS INSTRUMENTS; Mfr_name: TEXAS INSTRUMENTS; Mfr_part_number: LM5060MM/NOPB; Mistral Part No: 142015100007-R; Package: VSSOP10; Part_type: ICS\POWER\MANAGEMENT; Project: GALILEO_EVM; RoHS: RoHS; Temperature: -40°C+125°C; Tolerance: NA; Voltage: NA; Wattage: NA; Weight: NA; Datasheet: Y:\MIS_DATABASE\DATASHEETS\ICS\POWER\LM5060-TI.PDF

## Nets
DGND: C80.2 C130.2 C602.2 C603.2 C607.2 C643.1 C650.2 C666.2 C667.2 C678.2 C907.1 D29.2(ANODE) D41.2(ANODE) J3.1 J7.3 J7.4 J7.5 J7.6 J7.7 J7.SH1 J7.SH2 J7.SH3 J7.SH4 J24.3 LD4.1 R845.2 R849.2 R851.2 TP37.1(TP) TP96.1(TP) TP323.1(TP) TP324.1(TP) TP325.1(TP) TP326.1(TP) U16.2(GND) U179.2(SOURCE) U182.6(GND) ; also on sheet 11 12 13 14 15 16 17 18 20 21 22 23 24 25 26 27 28 29 30 31 32 33 34 35 36 37 38 39 40 41 42 43 44 45 46 47 48 49 50 51 52 53 54 55 56 57 58 59 60 61 62 63 65 66 67 68 69 70 71 72 73 76 77 78 79 81 82 83 84
VCC_12V0: C907.2 J24.2 ; also on sheet 30 31 46 50 53 59 60 66 83
VINPUT: C130.1 C667.1 C678.1 R3.1 R829.1 TP31.1(TP) U28.3(S) ; also on sheet 36 65 66 67
GATE: U16.6(GATE) U21.4(GATE)
LM5060_EN: J6.2 R830.2 R845.1 SW1.2 U182.5(EN)
LM5060_EN_HIGH: J6.1 R780.2 SW1.3
LM5060_EN_LOW: J6.3 SW1.1
LM5060_GATE: C643.2 U28.1(G) U182.10(GATE)
LM5060_nPGD: R830.1 R831.1 U182.8(NPGD)
LM5060_OUT: R829.2 U182.9(OUT)
LM5060_OVP: R850.2 R851.1 U182.3(OVP)
LM5060_SENSE: R846.2 U182.1(SENSE)
LM5060_TIMER: C650.1 U182.7(TIMER)
LM5060_ULVO: R847.2 R849.1 U182.4(UVLO)
VCAPL: C53.1 U16.4(VCAP)
VMAIN: C80.1 C602.1 C603.1 C607.1 C666.1 R4.1 R780.1 R846.1 R847.1 R850.1 TP20.1(TP) U21.5(D1) U28.4(D) U182.2(VIN)
VMAIN_CONN: D29.1(CATHODE) F1.1 J3.2 J7.1 J7.2
VMAIN_FUSE: C53.2 F1.2 U16.1(EN) U16.5(SOURCE) U21.1(S1) U21.2(S2) U21.3(S3)
N16818967: D41.1(CATHODE) R831.2 U179.1(GATE)
N23955014: LD4.2 R3.2
N24222943: LD5.1 U179.3(DRAIN)
N24223544: LD5.2 R4.2

Not connected (* = marked no-connect by the designer): F2 1 2; J24 1*; U16 3(NC1)* 7(NC2)* 8(NC3)*

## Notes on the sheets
sheet 64
- OVER VOLTAGE PROTECTION CIRCUIT
- Reverse Polarity protection CKT
- Provision for bench supply
- SPARE FUSE
- Power Input
- Normal operation Range for VINPUT 20.5V to 52V.
- ON/OFF Control Switch
- Fault Indication
- RED
- Silkscreen:"FAULT LED"
- Condition
- LED Status
- Ground test points
- VMAIN between 20.5 to 52V
- OFF
- Cooling FAN Header
- VMAIN beyond 52V or
  below 20.5V
- ON
- Silkscreen:"12V FAN"
- Note: When fault is indicated; set to proper voltage and power cycle the board.
- Mating Parts: 440129-3 & 1735801-1
